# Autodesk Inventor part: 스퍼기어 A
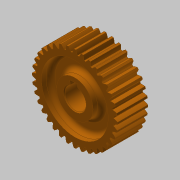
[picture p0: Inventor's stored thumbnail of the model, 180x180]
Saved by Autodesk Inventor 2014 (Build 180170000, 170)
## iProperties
Created: 2020-04
Part Number: 스퍼기어 A
Material: Steel
Document SubType Name: Modeling
Designer: mduedu
Categories: <?xml version="1.0" encoding="UTF-16"?> <MemberInstance><Categories><FamilyTemplate><FamilyTemplateParameter ValueType="xs:double" Id="1" ObjectReferenceKey="da
Density: 7.85 g/cm^3
Mass: 238.004 g
Surface Area: 130.635 cm^2
Volume: 30.319 cm^3
Appearance: Orange
CustomPartVersion: 1
Author: mduedu
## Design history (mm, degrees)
sketch "Sketch1"
  geometry: C1 r 28.2 at (0, 0)
  constraints: 1 centre point
  dimensions: "d0" = 56.4 diameter of C1 (= da_da)
extrude "Extrusion1" new body sketch "Sketch1" distance "d1" = 20 (= da_b); taper "d2" = 0 deg
workplane "Work Plane2"
sketch "Sketch2"
  geometry: C1 r 28.2 at (0, 0) reference; C2 r 27 at (0, 0)
  constraints: 1 centre point, 1 coincident
  dimensions: "d3" = 54 diameter of C2 (= da_dw)
feature "피치 지름" sketch "Sketch2" dims "d4" = 10, "d5" = 0
workplane "Work Plane8"
workplane "Work Plane9"
feature "스퍼 기어" dims "da_b" = 20, "da_d" = 54, "da_aw" = 45, "da_da" = 56.4, "da_df" = 51.129, "da_dw" = 54, angle "da_beta" = 0 deg, "da_lefttooth" = 0, "da_righttooth" = 0
node "작업 평면11"
sketch "스케치3"
  geometry: C1 r 12 at (0, 0); C2 r 22 at (0, 0); 1 further point
  constraints: 2 centre point, 2 coincident
  dimensions: "d49" = 24 diameter of C1; "d50" = 44 diameter of C2
extrude "돌출2" cut sketch "스케치3" distance "d51" = 6; taper "d52" = 0 deg
fillet "모깎기1" dims "d53" = 3
sketch "스케치4" dims "d17" = 0
  geometry: L1 (-3.06, 6.296)-(1.921, 6.731); L2 (1.921, 6.731)-(1.68, 9.483); L3 (1.68, 9.483)-(-3.301, 9.047); L4 (-3.301, 9.047)-(-3.06, 6.296); L5 (-3.728, 42.608)-(3.728, -42.608) reference; A1 r 7 centre (0, 0) between (-3.06, 6.296) and (1.921, 6.731); 1 further point
  constraints: 8 end point, 4 perpendicular, 2 point on circle, 1 centre point, 1 coincident
  dimensions: "d54" = 14 diameter of A1; "d63" = 16.3 dimension on A1 L3; "d64" = 5 distance of L2.end L3.end
extrude "돌출3" cut sketch "스케치4" stored distance "d58" = 6; taper "d59" = 0 deg
chamfer "모따기1" distance "d60" = 0.5; stored, may be unused: second distance "d61" = 2, angle "d62" = 45 deg
body "Solid1"
mirror "대칭1"
body "Srf1"
other parameters: "d16" = 45 (= da_aw), "d34" = 5 deg (computed from da_z), "d39" = 0, "d41" = 0, "d43" = 45 (= da_aw), "d46" = 45 (= da_aw), "d47" = 0, "d48" = 0
